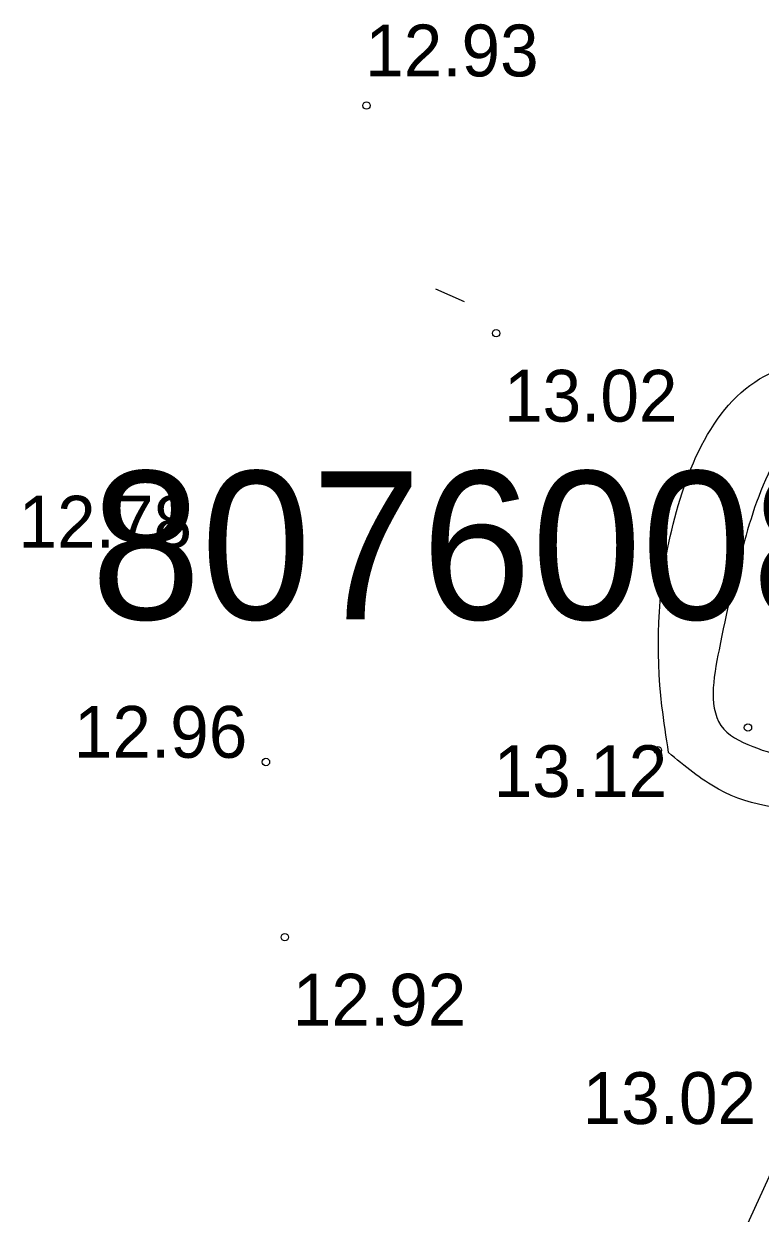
# Model space of a CAD drawing. Extents: x 503877 to 504025, y 304562 to 304725.
# Drawn here: x 503915.79 to 503925.74, y 304706.29 to 304722.35 of the extents above; entities that cross this region are included whole.
import ezdxf

# ---------------------------------------------------------------- set-up
doc = ezdxf.new("R2010")
doc.units = 0
for name, color, linetype in [('24', 7, 'Continuous'), ('Level 31', 7, 'Continuous'), ('NORB_ZOGS_SBST_####_#', 7, 'Continuous'), ('RELJ_AATZ_####_TKST_#', 7, 'Continuous'), ('RELJ_ELEM_####_####_#', 7, 'Continuous'), ('RELJ_HORZ_KRIT_####_#', 7, 'Continuous'), ('RELJ_NOGA_####_####_#', 7, 'Continuous')]:
    doc.layers.add(name, color=color, linetype=linetype)

msp = doc.modelspace()

# ---------------------------------------------------------------- linework, layer by layer
at = {"layer": 'Level 31'}
msp.add_spline([(503924.5, 304712.506), (503925.172, 304712.013), (503926.717, 304711.766), (503927.613, 304712.102), (503928.173, 304713.809), (503928.845, 304715.448), (503928.845, 304716.503), (503928.308, 304717.199), (503927.076, 304717.761), (503925.866, 304717.626), (503924.522, 304715.425), (503924.41, 304713.135), (503924.5, 304712.506)], degree=3, dxfattribs=at)
at = {"layer": 'NORB_ZOGS_SBST_####_#'}
msp.add_line((503928.336, 304712.215), (503920.857, 304695.837), dxfattribs=at)
at = {"layer": 'RELJ_ELEM_####_####_#'}
for centre in [(503920.42, 304721.245), (503922.17, 304718.17), (503925.571, 304712.844), (503924.354, 304712.538), (503919.062, 304712.379), (503919.318, 304710.014)]:
    msp.add_circle(centre, 0.05, dxfattribs=at)
at = {"layer": 'RELJ_HORZ_KRIT_####_#'}
msp.add_line((503921.744, 304718.594), (503921.356, 304718.766), dxfattribs=at)
msp.add_line((503921.744, 304718.594), (503921.356, 304718.766), dxfattribs=at)
at = {"layer": 'RELJ_NOGA_####_####_#'}
msp.add_spline([(503927.57, 304716.939), (503927.322, 304717.112), (503926.77, 304717.242), (503925.959, 304716.495), (503925.504, 304715.293), (503925.18, 304713.896), (503925.244, 304712.824), (503925.699, 304712.564), (503926.218, 304712.434), (503926.835, 304712.532), (503927.16, 304712.857), (503927.354, 304713.311), (503927.708, 304714.28)], degree=3, dxfattribs=at)

# ---------------------------------------------------------------- texts
at = {"layer": '24'}
msp.add_text('80760080055', height=2, dxfattribs=at).set_placement((503916.698, 304714.306))
at = {"layer": 'RELJ_AATZ_####_TKST_#'}
for s, p in [('12.93', (503920.402, 304721.639)), ('13.02', (503922.277, 304716.976)), ('12.78', (503915.721, 304715.275)), ('12.96', (503916.468, 304712.436)), ('13.12', (503922.138, 304711.905)), ('12.92', (503919.425, 304708.819)), ('13.02', (503923.338, 304707.49))]:
    msp.add_text(s, height=0.7, dxfattribs=at).set_placement(p)

doc.saveas('drawing.dxf')
